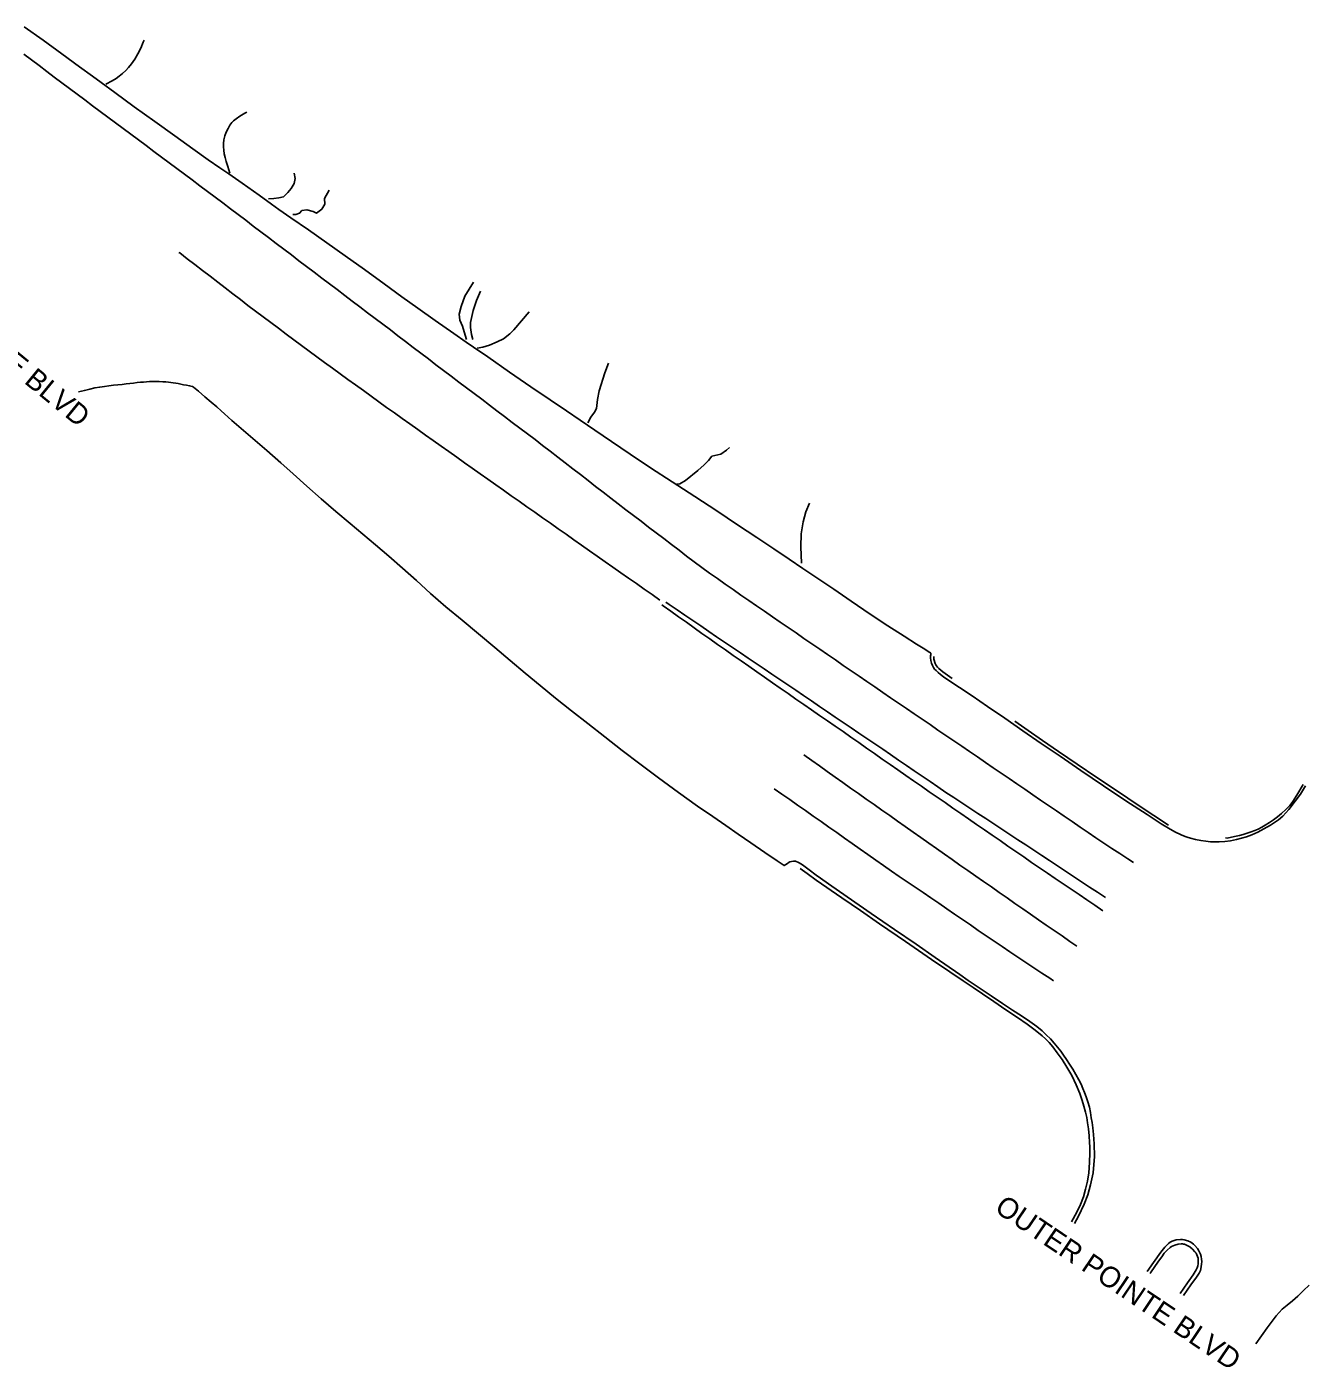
# Model space of a CAD drawing. Extents: x 1961683 to 1977751, y 798292 to 805767.
# Drawn here: x 1962037.9 to 1962372.5, y 800185.7 to 800536 of the extents above; entities that cross this region are included whole.
import ezdxf

# ---------------------------------------------------------------- set-up
doc = ezdxf.new("R2010")
doc.units = 0
for name, color, linetype in [('RD_EX_Conc', 7, 'Continuous'), ('RD_EX_Driveway', 7, 'Continuous'), ('RD_EX_Road', 7, 'Continuous'), ('RD_EX_Road_Paint', 7, 'Continuous'), ('RD_TX_RoadID', 7, 'Continuous')]:
    doc.layers.add(name, color=color, linetype=linetype)

msp = doc.modelspace()

# ---------------------------------------------------------------- linework, layer by layer
at = {"layer": 'RD_EX_Conc'}
msp.add_lwpolyline([(1962340.16, 800204.36), (1962342.1, 800207.16), (1962343.51, 800209.18), (1962344.21, 800210.22), (1962344.43, 800210.56), (1962344.58, 800210.9), (1962344.71, 800211.35), (1962344.88, 800212.57), (1962344.91, 800213.27), (1962344.86, 800213.93), (1962344.75, 800214.56), (1962344.57, 800215.16), (1962344.08, 800216.23), (1962343.78, 800216.7), (1962343.11, 800217.5), (1962342.76, 800217.83), (1962342.4, 800218.11), (1962342.03, 800218.34), (1962341.25, 800218.69), (1962340.35, 800218.93), (1962339.86, 800219), (1962339.35, 800219.02), (1962338.26, 800218.92), (1962337.7, 800218.78), (1962337.18, 800218.58), (1962336.69, 800218.3), (1962336.24, 800217.95), (1962335.29, 800217.01), (1962334.23, 800215.72), (1962332.33, 800213.06), (1962330.66, 800210.63)], dxfattribs=at)
at = {"layer": 'RD_EX_Driveway'}
for points in [[(1962101.1, 800491), (1962102.44, 800491.07), (1962103.75, 800491.23), (1962104.97, 800491.54), (1962106.1, 800492.67), (1962106.96, 800493.71), (1962107.75, 800495.02), (1962108.03, 800496.33), (1962107.75, 800497.68)], [(1962156.5, 800466.83), (1962155.44, 800464.43), (1962154.58, 800461.8), (1962153.86, 800458.67), (1962153.84, 800457.34), (1962154.16, 800455.54), (1962154.43, 800454.27)]]:
    msp.add_lwpolyline(points, dxfattribs=at)
at = {"layer": 'RD_EX_Road'}
for points in [[(1962037.24, 800535.96), (1962042.18, 800532.46), (1962047.09, 800528.92), (1962051.71, 800525.53), (1962055.06, 800523.08), (1962057.37, 800521.42), (1962060.96, 800518.8), (1962066.02, 800515.08), (1962071.34, 800511.23), (1962076.63, 800507.44), (1962081.32, 800504.07), (1962085.31, 800501.2), (1962088.35, 800499.08), (1962090.72, 800497.52), (1962094.18, 800495.12), (1962098.65, 800491.93), (1962101.84, 800489.64), (1962103.78, 800488.25), (1962106.94, 800486.04), (1962111.52, 800482.86), (1962116.3, 800479.52), (1962121.11, 800476.12), (1962126.14, 800472.52), (1962131.31, 800468.78), (1962135.95, 800465.42), (1962140.09, 800462.41), (1962144.64, 800459.18), (1962149.47, 800455.81), (1962152.73, 800453.57), (1962154.65, 800452.28), (1962158.37, 800449.68), (1962164.07, 800445.67), (1962169.64, 800441.83), (1962174.67, 800438.43), (1962178.92, 800435.57), (1962182.5, 800433.17), (1962186.38, 800430.54), (1962190.74, 800427.58), (1962195.59, 800424.3), (1962200.92, 800420.74), (1962206.58, 800417.02), (1962212.49, 800413.19), (1962218.21, 800409.45), (1962223.66, 800405.84), (1962228.63, 800402.52), (1962233.1, 800399.51), (1962237.1, 800396.81), (1962240.73, 800394.35), (1962244.58, 800391.76), (1962248.78, 800388.96), (1962253.36, 800385.85), (1962258.26, 800382.49), (1962262.91, 800379.4), (1962267.14, 800376.7), (1962270.38, 800374.64), (1962272.54, 800373.27), (1962273.71, 800372.53), (1962274.01, 800372.33), (1962274.12, 800372.26), (1962274.17, 800372.22), (1962274.19, 800372.16), (1962274.17, 800372.07), (1962274.12, 800371.87), (1962274.06, 800371.54), (1962274.05, 800371.03), (1962274.12, 800370.36), (1962274.29, 800369.69), (1962274.55, 800369.04), (1962274.82, 800368.52), (1962275.09, 800368.12), (1962275.49, 800367.7), (1962276.03, 800367.23), (1962276.66, 800366.71), (1962277.48, 800366.08), (1962279.09, 800364.97), (1962281.59, 800363.32), (1962284.91, 800361.08), (1962288.98, 800358.31), (1962293.44, 800355.25), (1962298.19, 800351.99), (1962303, 800348.69), (1962307.9, 800345.33), (1962313.31, 800341.64), (1962319.22, 800337.62), (1962325.11, 800333.69), (1962330.64, 800330.06), (1962334.35, 800327.67), (1962336.24, 800326.52), (1962337.91, 800325.61), (1962339.54, 800324.8), (1962340.59, 800324.33), (1962341.12, 800324.15), (1962341.99, 800323.92), (1962343.3, 800323.59), (1962344.66, 800323.31), (1962345.99, 800323.1), (1962347.18, 800322.99), (1962348.25, 800322.97), (1962349.49, 800322.99), (1962350.92, 800323.06), (1962352.43, 800323.24), (1962353.96, 800323.54), (1962355.34, 800323.88), (1962356.61, 800324.28), (1962358, 800324.82), (1962359.56, 800325.52), (1962361.17, 800326.34), (1962362.88, 800327.33), (1962364.93, 800328.75), (1962366.1, 800329.63), (1962367.7, 800331.38), (1962370.68, 800335.45), (1962371.99, 800337.57)], [(1962058.56, 800520.99), (1962060.22, 800521.83), (1962061.25, 800522.48), (1962062.02, 800523.07), (1962062.89, 800523.75), (1962063.76, 800524.51), (1962064.52, 800525.31), (1962065.27, 800526.26), (1962066.12, 800527.51), (1962066.97, 800528.91), (1962067.71, 800530.37), (1962068.37, 800531.92), (1962068.56, 800532.43)], [(1962090.96, 800497.69), (1962090.42, 800499.41), (1962090.02, 800500.72), (1962089.73, 800501.79), (1962089.52, 800502.77), (1962089.37, 800503.7), (1962089.29, 800504.58), (1962089.3, 800505.48), (1962089.42, 800506.44), (1962089.67, 800507.44), (1962090.05, 800508.46), (1962090.51, 800509.42), (1962091, 800510.26), (1962091.49, 800510.94), (1962091.95, 800511.43), (1962092.59, 800511.92), (1962093.59, 800512.58), (1962094.88, 800513.36), (1962095.42, 800513.67)], [(1962116.93, 800493.29), (1962115.75, 800491.08), (1962115.78, 800489.58), (1962114.99, 800488.34), (1962113.61, 800487.29), (1962112.76, 800487.65), (1962111.1, 800488.1), (1962109.82, 800487.95), (1962109.18, 800487.25), (1962108.22, 800486.92), (1962107.43, 800486.94)], [(1962154.67, 800469.2), (1962152.37, 800465.53), (1962151.38, 800462.86), (1962150.93, 800460.85), (1962151.1, 800459.25), (1962151.78, 800457.76), (1962152.2, 800456.24), (1962152.83, 800454.22)], [(1962169.17, 800461.5), (1962165.18, 800456.77), (1962164.09, 800455.76), (1962162.52, 800454.43), (1962160.81, 800453.63), (1962158.86, 800452.8), (1962157.12, 800452.2), (1962155.56, 800452.01)], [(1962189.94, 800448.06), (1962188.99, 800445.49), (1962187.45, 800440.79), (1962187.06, 800438.52), (1962186.77, 800436.22), (1962186.24, 800435.24), (1962185.3, 800433.95), (1962184.52, 800432.42)], [(1962051.44, 800440.52), (1962052.96, 800440.94), (1962054.39, 800441.29), (1962055.74, 800441.57), (1962057, 800441.79), (1962058.21, 800441.96), (1962059.4, 800442.12), (1962060.57, 800442.27), (1962061.71, 800442.39), (1962062.83, 800442.51), (1962063.88, 800442.63), (1962064.89, 800442.74), (1962065.84, 800442.85), (1962066.75, 800442.96), (1962067.61, 800443.05), (1962068.43, 800443.13), (1962069.2, 800443.19), (1962069.98, 800443.23), (1962070.79, 800443.26), (1962071.65, 800443.26), (1962072.55, 800443.23), (1962073.43, 800443.19), (1962074.23, 800443.14), (1962074.95, 800443.08), (1962075.59, 800443.01), (1962076.2, 800442.93), (1962076.83, 800442.83), (1962077.49, 800442.71), (1962078.17, 800442.57), (1962078.88, 800442.42), (1962079.65, 800442.31), (1962080.44, 800442.17), (1962081.1, 800441.97), (1962081.23, 800441.93), (1962081.45, 800441.76), (1962082.79, 800440.72), (1962084.48, 800439.3), (1962086.13, 800437.88), (1962087.56, 800436.66), (1962088.73, 800435.64), (1962089.61, 800434.82), (1962091.51, 800433.11), (1962095.78, 800429.42), (1962100.63, 800425.23), (1962104.29, 800422.02), (1962107.52, 800419.14), (1962111.1, 800415.93), (1962114.87, 800412.58), (1962118.7, 800409.28), (1962122.38, 800406.17), (1962125.72, 800403.35), (1962129, 800400.59), (1962132.5, 800397.61), (1962136.11, 800394.47), (1962139.71, 800391.22), (1962143.44, 800387.85), (1962147.45, 800384.4), (1962151.66, 800380.87), (1962155.98, 800377.28), (1962160.23, 800373.75), (1962164.25, 800370.37), (1962168.15, 800367.07), (1962172.09, 800363.78), (1962176.1, 800360.5), (1962180.23, 800357.23), (1962184.5, 800353.89), (1962188.95, 800350.39), (1962193.51, 800346.84), (1962198.14, 800343.32), (1962203, 800339.7), (1962208.23, 800335.86), (1962213.17, 800332.31), (1962217.15, 800329.55), (1962220.57, 800327.23), (1962223.8, 800325), (1962227.12, 800322.71), (1962230.79, 800320.19), (1962233.98, 800318.01), (1962235.83, 800316.75), (1962236.64, 800317.3), (1962237.14, 800317.61), (1962237.33, 800317.7), (1962237.77, 800317.84), (1962238.28, 800317.93), (1962238.52, 800317.93), (1962238.75, 800317.9), (1962238.96, 800317.83), (1962239.35, 800317.66), (1962239.73, 800317.48), (1962240.57, 800316.94), (1962242.35, 800315.65), (1962244.21, 800314.28), (1962245.28, 800313.5), (1962247.37, 800312.02), (1962252.29, 800308.57), (1962258.54, 800304.21), (1962264.62, 800300.04), (1962270.28, 800296.17), (1962275.25, 800292.75), (1962278.88, 800290.24), (1962280.54, 800289.08), (1962281.72, 800288.26), (1962283.93, 800286.75), (1962286.79, 800284.82), (1962289.88, 800282.74), (1962292.89, 800280.72), (1962295.5, 800278.99), (1962297.82, 800277.45), (1962299.99, 800275.99), (1962301.83, 800274.68), (1962303.18, 800273.59), (1962304.27, 800272.56), (1962305.36, 800271.47), (1962306.39, 800270.36), (1962307.27, 800269.29), (1962308.06, 800268.24), (1962308.8, 800267.18), (1962309.56, 800266.06), (1962310.38, 800264.83), (1962311.23, 800263.52), (1962312.06, 800262.13), (1962312.81, 800260.79), (1962313.4, 800259.59), (1962313.88, 800258.49), (1962314.32, 800257.45), (1962314.74, 800256.34), (1962315.18, 800255.04), (1962315.58, 800253.65), (1962315.85, 800252.23), (1962316.06, 800250.85), (1962316.25, 800249.59), (1962316.43, 800248.2), (1962316.63, 800246.44), (1962316.8, 800244.04), (1962316.9, 800240.74), (1962316.52, 800236.48), (1962315.89, 800233.31), (1962315.13, 800230.73), (1962314.2, 800228.28), (1962312.73, 800225.16), (1962311.66, 800223.18)], [(1962221.57, 800426.03), (1962220.74, 800425.34), (1962219.28, 800424.31), (1962216.95, 800423.75), (1962216.06, 800422.66), (1962214.91, 800421.51), (1962213.29, 800420), (1962210, 800417.4), (1962208.55, 800416.56), (1962207.81, 800416.39)], [(1962242.47, 800411.45), (1962241.47, 800409.23), (1962240.75, 800406.6), (1962240.24, 800403.47), (1962240.14, 800400.09), (1962240.32, 800395.82)], [(1962274.92, 800371.41), (1962274.95, 800370.71), (1962275.3, 800369.59), (1962275.45, 800369.22), (1962275.59, 800368.97), (1962275.88, 800368.6), (1962276.2, 800368.24), (1962277.25, 800367.4), (1962279.74, 800365.61)], [(1962336.25, 800327.31), (1962328.55, 800332.36), (1962322.61, 800336.33), (1962317.52, 800339.79), (1962312.38, 800343.29), (1962307.53, 800346.6), (1962303.34, 800349.46), (1962299.58, 800352.04), (1962296.04, 800354.51)], [(1962351.1, 800323.96), (1962351.53, 800323.93), (1962353.45, 800324.35), (1962354.74, 800324.64), (1962355.74, 800324.89), (1962356.79, 800325.19), (1962357.83, 800325.53), (1962358.77, 800325.9), (1962359.68, 800326.31), (1962360.58, 800326.78), (1962361.53, 800327.33), (1962362.61, 800328.01), (1962363.7, 800328.75), (1962364.71, 800329.52), (1962365.73, 800330.37), (1962366.86, 800331.41), (1962367.91, 800332.49), (1962368.7, 800333.49), (1962369.77, 800335.18), (1962371.41, 800337.91)], [(1962310.91, 800223.68), (1962312.26, 800226.14), (1962313.24, 800228.2), (1962313.98, 800230.16), (1962314.57, 800232.2), (1962315.04, 800234.28), (1962315.39, 800236.47), (1962315.61, 800239.19), (1962315.7, 800241.7), (1962315.7, 800243.27), (1962315.63, 800244.36), (1962315.48, 800246.1), (1962315.29, 800247.99), (1962315.09, 800249.5), (1962314.85, 800250.87), (1962314.54, 800252.35), (1962314.15, 800253.87), (1962313.68, 800255.38), (1962313.03, 800257.16), (1962312.08, 800259.48), (1962310.93, 800261.93), (1962309.69, 800264.11), (1962308.42, 800266.06), (1962307.18, 800267.83), (1962306.03, 800269.35), (1962305.01, 800270.54), (1962304.09, 800271.49), (1962303.25, 800272.26), (1962302.3, 800273.05), (1962301.08, 800274.01), (1962299.32, 800275.29), (1962296.77, 800277.04), (1962293.75, 800279.07), (1962290.59, 800281.2), (1962287.63, 800283.2), (1962285.17, 800284.86), (1962282.56, 800286.63), (1962279.13, 800288.96), (1962274.31, 800292.24), (1962267.54, 800296.87), (1962260.73, 800301.55), (1962255.78, 800304.97), (1962250.89, 800308.35), (1962244.21, 800312.94), (1962241.82, 800314.7), (1962240.03, 800315.98)], [(1962339.28, 800204.94), (1962341.21, 800207.67), (1962342.66, 800209.79), (1962343.43, 800211.07), (1962343.68, 800211.62), (1962343.87, 800212.16), (1962343.97, 800212.68), (1962344.02, 800213.19), (1962344, 800213.68), (1962343.94, 800214.15), (1962343.81, 800214.6), (1962343.64, 800215.03), (1962343.42, 800215.44), (1962343.15, 800215.83), (1962342.5, 800216.52), (1962341.81, 800217.07), (1962341.09, 800217.49), (1962340.45, 800217.77), (1962340.16, 800217.85), (1962339.87, 800217.89), (1962339.53, 800217.9), (1962338.74, 800217.81), (1962337.88, 800217.56), (1962337.05, 800217.17), (1962336.64, 800216.91), (1962335.87, 800216.26), (1962335.14, 800215.42), (1962334.46, 800214.54), (1962333.66, 800213.37), (1962331.55, 800210.29), (1962331.43, 800210.12)], [(1962359.01, 800191.79), (1962362.05, 800195.98), (1962364.32, 800199.06), (1962365.92, 800200.83), (1962367.26, 800201.89), (1962368.6, 800202.99), (1962370, 800204.25), (1962371.5, 800205.66), (1962372.95, 800207.09)]]:
    msp.add_lwpolyline(points, dxfattribs=at)
at = {"layer": 'RD_EX_Road_Paint'}
for points in [[(1962037.13, 800528.83), (1962039.13, 800527.33), (1962041.12, 800525.82), (1962043.12, 800524.32), (1962045.11, 800522.82), (1962047.11, 800521.32), (1962049.11, 800519.82), (1962051.11, 800518.33), (1962053.12, 800516.84), (1962055.12, 800515.35), (1962057.13, 800513.86), (1962059.13, 800512.37), (1962061.14, 800510.88), (1962063.14, 800509.39), (1962065.15, 800507.9), (1962067.15, 800506.4), (1962069.15, 800504.91), (1962071.15, 800503.41), (1962073.15, 800501.92), (1962075.15, 800500.42), (1962077.15, 800498.93), (1962079.16, 800497.43), (1962081.16, 800495.93), (1962083.16, 800494.44), (1962085.16, 800492.94), (1962087.16, 800491.45), (1962089.15, 800489.94), (1962091.14, 800488.43), (1962093.13, 800486.92), (1962095.12, 800485.41), (1962097.11, 800483.89), (1962099.09, 800482.38), (1962101.08, 800480.87), (1962103.07, 800479.36), (1962105.06, 800477.85), (1962107.05, 800476.33), (1962109.03, 800474.82), (1962111.02, 800473.31), (1962113.01, 800471.8), (1962115, 800470.3), (1962116.99, 800468.79), (1962118.99, 800467.28), (1962120.98, 800465.77), (1962122.97, 800464.26), (1962124.96, 800462.76), (1962126.95, 800461.25), (1962128.94, 800459.74), (1962130.93, 800458.23), (1962132.92, 800456.73), (1962134.91, 800455.21), (1962136.89, 800453.7), (1962138.88, 800452.19), (1962140.87, 800450.68), (1962142.86, 800449.17), (1962144.84, 800447.65), (1962146.83, 800446.14), (1962148.82, 800444.63), (1962150.81, 800443.13), (1962152.8, 800441.62), (1962154.79, 800440.12), (1962156.78, 800438.61), (1962158.78, 800437.11), (1962160.77, 800435.6), (1962162.76, 800434.1), (1962164.75, 800432.59), (1962166.75, 800431.09), (1962168.74, 800429.58), (1962170.73, 800428.08), (1962172.71, 800426.55), (1962174.68, 800425.03), (1962176.66, 800423.5), (1962178.63, 800421.97), (1962180.61, 800420.44), (1962182.58, 800418.92), (1962184.56, 800417.39), (1962186.53, 800415.86), (1962188.51, 800414.33), (1962190.48, 800412.81), (1962192.46, 800411.28), (1962194.44, 800409.76), (1962196.43, 800408.25), (1962198.41, 800406.74), (1962200.4, 800405.22), (1962202.39, 800403.71), (1962204.37, 800402.19), (1962206.36, 800400.68), (1962208.34, 800399.17), (1962210.33, 800397.65), (1962212.31, 800396.14), (1962214.3, 800394.63), (1962216.33, 800393.17), (1962218.38, 800391.75), (1962220.43, 800390.32), (1962222.47, 800388.89), (1962224.52, 800387.46), (1962226.57, 800386.03), (1962228.61, 800384.61), (1962230.67, 800383.2), (1962232.73, 800381.78), (1962234.79, 800380.37), (1962236.85, 800378.96), (1962238.91, 800377.55), (1962240.97, 800376.14), (1962243.03, 800374.73), (1962245.09, 800373.32), (1962247.15, 800371.9), (1962249.21, 800370.49), (1962251.27, 800369.08), (1962253.32, 800367.67), (1962255.38, 800366.26), (1962257.44, 800364.85), (1962259.5, 800363.43), (1962261.56, 800362.02), (1962263.63, 800360.62), (1962265.69, 800359.21), (1962267.75, 800357.8), (1962269.82, 800356.39), (1962271.88, 800354.98), (1962273.94, 800353.58), (1962276, 800352.17), (1962278.07, 800350.76), (1962280.13, 800349.35), (1962282.19, 800347.95), (1962284.26, 800346.54), (1962286.32, 800345.13), (1962288.38, 800343.72), (1962290.45, 800342.31), (1962292.51, 800340.91), (1962294.57, 800339.5), (1962296.63, 800338.09), (1962298.7, 800336.68), (1962300.76, 800335.27), (1962302.82, 800333.86), (1962304.89, 800332.45), (1962306.95, 800331.04), (1962309.01, 800329.63), (1962311.07, 800328.23), (1962313.14, 800326.82), (1962315.2, 800325.41), (1962317.26, 800324), (1962319.33, 800322.6), (1962321.43, 800321.24), (1962323.52, 800319.88), (1962325.62, 800318.51), (1962327.12, 800317.54)], [(1962203.33, 800386.13), (1962201.29, 800387.57), (1962199.24, 800389), (1962197.2, 800390.43), (1962195.16, 800391.87), (1962193.11, 800393.3), (1962191.07, 800394.73), (1962189.02, 800396.17), (1962186.98, 800397.6), (1962184.93, 800399.03), (1962182.89, 800400.47), (1962180.85, 800401.91), (1962178.81, 800403.35), (1962176.77, 800404.79), (1962174.73, 800406.22), (1962172.69, 800407.66), (1962170.65, 800409.1), (1962168.61, 800410.54), (1962166.56, 800411.98), (1962164.52, 800413.41), (1962162.48, 800414.85), (1962160.44, 800416.29), (1962158.4, 800417.73), (1962156.36, 800419.17), (1962154.32, 800420.61), (1962152.29, 800422.05), (1962150.25, 800423.5), (1962148.21, 800424.94), (1962146.18, 800426.39), (1962144.14, 800427.83), (1962142.1, 800429.27), (1962140.07, 800430.72), (1962138.03, 800432.16), (1962135.99, 800433.61), (1962133.96, 800435.05), (1962131.93, 800436.51), (1962129.91, 800437.97), (1962127.88, 800439.44), (1962125.86, 800440.9), (1962123.84, 800442.36), (1962121.81, 800443.83), (1962119.79, 800445.29), (1962117.77, 800446.75), (1962115.74, 800448.22), (1962113.72, 800449.68), (1962111.72, 800451.18), (1962109.72, 800452.68), (1962107.72, 800454.17), (1962105.72, 800455.67), (1962103.72, 800457.16), (1962101.72, 800458.66), (1962099.72, 800460.16), (1962097.72, 800461.65), (1962095.72, 800463.15), (1962093.74, 800464.67), (1962091.76, 800466.19), (1962089.78, 800467.72), (1962087.8, 800469.24), (1962085.82, 800470.76), (1962083.84, 800472.28), (1962081.86, 800473.8), (1962079.87, 800475.32), (1962077.89, 800476.85), (1962077.69, 800477)], [(1962319.06, 800304.96), (1962316.99, 800306.37), (1962314.92, 800307.77), (1962312.86, 800309.17), (1962310.79, 800310.58), (1962308.72, 800311.98), (1962306.65, 800313.38), (1962304.59, 800314.79), (1962302.52, 800316.19), (1962300.46, 800317.59), (1962298.4, 800319.01), (1962296.35, 800320.43), (1962294.29, 800321.85), (1962292.24, 800323.27), (1962290.18, 800324.69), (1962288.13, 800326.11), (1962286.07, 800327.53), (1962284.01, 800328.95), (1962281.96, 800330.37), (1962279.9, 800331.79), (1962277.85, 800333.21), (1962275.79, 800334.63), (1962273.74, 800336.05), (1962271.68, 800337.47), (1962269.63, 800338.88), (1962267.58, 800340.31), (1962265.53, 800341.74), (1962263.49, 800343.17), (1962261.44, 800344.6), (1962259.39, 800346.03), (1962257.35, 800347.46), (1962255.3, 800348.89), (1962253.25, 800350.32), (1962251.2, 800351.75), (1962249.15, 800353.17), (1962247.1, 800354.59), (1962245.04, 800356.01), (1962242.99, 800357.44), (1962240.94, 800358.86), (1962238.89, 800360.28), (1962236.84, 800361.7), (1962234.79, 800363.13), (1962232.74, 800364.55), (1962230.69, 800365.98), (1962228.64, 800367.4), (1962226.59, 800368.83), (1962224.54, 800370.25), (1962222.49, 800371.68), (1962220.44, 800373.1), (1962218.4, 800374.55), (1962216.37, 800375.99), (1962214.33, 800377.44), (1962212.3, 800378.89), (1962210.26, 800380.33), (1962208.23, 800381.78), (1962206.19, 800383.23), (1962204.16, 800384.67), (1962203.83, 800384.91)], [(1962319.77, 800308.4), (1962317.69, 800309.77), (1962315.61, 800311.15), (1962313.52, 800312.53), (1962311.44, 800313.91), (1962309.36, 800315.29), (1962307.27, 800316.67), (1962305.18, 800318.04), (1962303.1, 800319.41), (1962301.01, 800320.78), (1962298.92, 800322.15), (1962296.83, 800323.52), (1962294.74, 800324.89), (1962292.66, 800326.26), (1962290.57, 800327.64), (1962288.49, 800329.02), (1962286.4, 800330.39), (1962284.32, 800331.77), (1962282.23, 800333.14), (1962280.15, 800334.52), (1962278.06, 800335.89), (1962275.99, 800337.29), (1962273.93, 800338.7), (1962271.87, 800340.11), (1962269.81, 800341.52), (1962267.75, 800342.93), (1962265.68, 800344.34), (1962263.62, 800345.74), (1962261.56, 800347.15), (1962259.5, 800348.56), (1962257.43, 800349.96), (1962255.36, 800351.36), (1962253.3, 800352.76), (1962251.23, 800354.16), (1962249.16, 800355.57), (1962247.1, 800356.97), (1962245.03, 800358.37), (1962242.97, 800359.77), (1962240.9, 800361.17), (1962238.83, 800362.57), (1962236.76, 800363.97), (1962234.7, 800365.37), (1962232.63, 800366.77), (1962230.56, 800368.17), (1962228.49, 800369.56), (1962226.43, 800370.96), (1962224.36, 800372.36), (1962222.29, 800373.76), (1962220.23, 800375.17), (1962218.16, 800376.57), (1962216.09, 800377.97), (1962214.03, 800379.37), (1962211.96, 800380.77), (1962209.9, 800382.17), (1962207.83, 800383.57), (1962205.76, 800384.97), (1962204.86, 800385.59)], [(1962240.97, 800345.71), (1962243, 800344.25), (1962245.04, 800342.8), (1962247.07, 800341.35), (1962249.1, 800339.9), (1962251.14, 800338.46), (1962253.18, 800337.02), (1962255.22, 800335.57), (1962257.26, 800334.13), (1962259.3, 800332.69), (1962261.34, 800331.25), (1962263.38, 800329.81), (1962265.42, 800328.37), (1962267.46, 800326.93), (1962269.5, 800325.5), (1962271.55, 800324.07), (1962273.6, 800322.64), (1962275.65, 800321.21), (1962277.68, 800319.76), (1962279.71, 800318.3), (1962281.75, 800316.87), (1962283.81, 800315.45), (1962285.86, 800314.02), (1962287.9, 800312.59), (1962289.95, 800311.16), (1962291.99, 800309.72), (1962294.04, 800308.29), (1962296.09, 800306.86), (1962298.15, 800305.45), (1962300.2, 800304.03), (1962302.25, 800302.6), (1962304.29, 800301.16), (1962306.36, 800299.75), (1962308.43, 800298.36), (1962310.49, 800296.94), (1962312.31, 800295.68)], [(1962233.19, 800336.85), (1962235.24, 800335.42), (1962237.28, 800333.99), (1962239.33, 800332.56), (1962241.37, 800331.12), (1962243.42, 800329.68), (1962245.46, 800328.24), (1962247.5, 800326.81), (1962249.54, 800325.37), (1962251.58, 800323.93), (1962253.62, 800322.49), (1962255.66, 800321.05), (1962257.7, 800319.61), (1962259.74, 800318.17), (1962261.79, 800316.74), (1962263.84, 800315.32), (1962265.9, 800313.9), (1962267.96, 800312.5), (1962270.03, 800311.1), (1962272.09, 800309.69), (1962274.16, 800308.29), (1962276.23, 800306.89), (1962278.29, 800305.48), (1962280.35, 800304.06), (1962282.4, 800302.64), (1962284.46, 800301.23), (1962286.52, 800299.82), (1962288.59, 800298.42), (1962290.66, 800297.02), (1962292.73, 800295.63), (1962294.81, 800294.23), (1962296.88, 800292.85), (1962298.96, 800291.46), (1962301.03, 800290.06), (1962303.11, 800288.67), (1962305.19, 800287.29), (1962306.21, 800286.61)]]:
    msp.add_lwpolyline(points, dxfattribs=at)

# ---------------------------------------------------------------- texts
at = {"layer": 'RD_TX_RoadID'}
for s, rotation, p in [('EXECUTIVE POINTE BLVD', 320.6752, (1961981.44, 800488.52)), ('OUTER POINTE BLVD', 326.0371, (1962290.51, 800226.49))]:
    msp.add_text(s, height=5.4, rotation=rotation, dxfattribs=at).set_placement(p)

doc.saveas('drawing.dxf')
